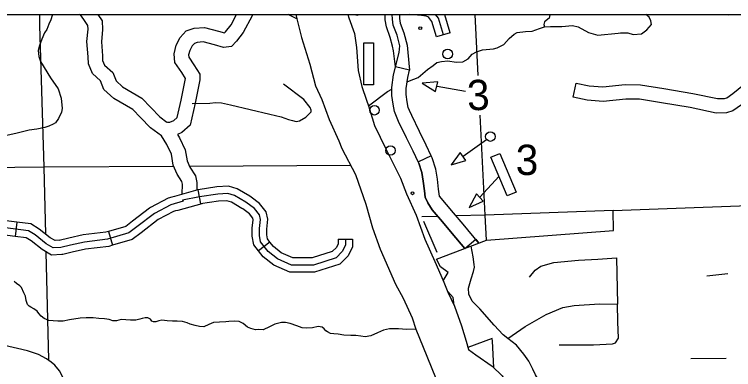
# Model space of a CAD drawing. Extents: x 22866 to 28196, y 1324810 to 1328105.
# Drawn here: x 25465.4 to 25645.9, y 1326492.6 to 1326581.6 of the extents above; entities that cross this region are included whole.
import ezdxf

# ---------------------------------------------------------------- set-up
doc = ezdxf.new("R2010")
doc.units = 0
for name, color, linetype in [('Level 10', 7, 'Continuous'), ('Level 31', 7, 'Continuous'), ('Level 32', 7, 'Continuous'), ('Level 33', 7, 'Continuous'), ('Level 34', 7, 'Continuous'), ('Level 35', 7, 'Continuous'), ('Level 43', 7, 'Continuous'), ('Level 45', 7, 'Continuous'), ('Level 46', 7, 'Continuous'), ('Level 5', 7, 'Continuous'), ('Level 56', 7, 'Continuous'), ('Level 6', 7, 'Continuous'), ('Level 9', 7, 'Continuous'), ('R_No Plot', 7, 'Continuous')]:
    doc.layers.add(name, color=color, linetype=linetype)

msp = doc.modelspace()

# ---------------------------------------------------------------- linework, layer by layer
at = {"layer": 'Level 10'}
msp.add_lwpolyline([(25483.97, 1326486.04), (25481.75, 1326486.89), (25480.32, 1326487.75), (25479.48, 1326488.37), (25478.6, 1326489.1), (25478.14, 1326489.62), (25477.72, 1326490.32), (25476.7, 1326492.23), (25475.5, 1326493.72), (25474.58, 1326494.45), (25473.43, 1326495.3), (25471.42, 1326496.33), (25468.7, 1326497.28), (25466.13, 1326497.87), (25462.9, 1326498.6), (25457.93, 1326499.47), (25456.22, 1326499.8), (25452.62, 1326500.3), (25449.84, 1326500.5), (25447.36, 1326500.74), (25445.63, 1326500.86), (25443.19, 1326500.9), (25441.23, 1326500.79)], dxfattribs=at)
at = {"layer": 'Level 31'}
for p, q in [((25564.54, 1326567.62), (25561.05, 1326568.49)), ((25569.99, 1326546.15), (25566.76, 1326544.65)), ((25578.38, 1326522.93), (25581.15, 1326525.23)), ((25581.15, 1326525.23), (25581.93, 1326524.29))]:
    msp.add_line(p, q, dxfattribs=at)
for points in [[(25558.42, 1326580.72), (25558.4, 1326581.62)], [(25561.05, 1326568.49), (25560.5, 1326572.48), (25560.3, 1326573.63), (25559.71, 1326575.86), (25558.72, 1326578.47), (25558.43, 1326580.29), (25558.42, 1326580.72)], [(25562, 1326581.62), (25562.02, 1326580.8)], [(25562.02, 1326580.8), (25562.03, 1326580.61), (25562.22, 1326579.4), (25563.14, 1326576.96), (25563.95, 1326573.92), (25564.14, 1326572.03), (25564.54, 1326567.62)], [(25561.26, 1326556.06), (25560.75, 1326557.24), (25560.4, 1326559.14), (25560.13, 1326561.27), (25560.09, 1326563.26), (25560.54, 1326566.46), (25561.05, 1326568.49)], [(25564.56, 1326557.5), (25564.21, 1326558.3), (25563.96, 1326559.69), (25563.72, 1326561.53), (25563.7, 1326563.04), (25564.08, 1326565.77), (25564.54, 1326567.62)], [(25569.99, 1326546.15), (25568.73, 1326548.86), (25567.04, 1326552.26), (25565.08, 1326556.3), (25564.56, 1326557.5)], [(25566.73, 1326544.63), (25565.49, 1326547.3), (25563.8, 1326550.67), (25561.81, 1326554.8), (25561.26, 1326556.06)], [(25566.73, 1326544.63), (25566.86, 1326544.34), (25567.65, 1326542), (25567.96, 1326539.8), (25568.27, 1326537.35), (25568.48, 1326535.84), (25569.1, 1326534.36), (25570.24, 1326532.64)], [(25572.08, 1326536.04), (25571.84, 1326537.82), (25571.53, 1326540.28), (25571.17, 1326542.84), (25570.21, 1326545.68), (25569.99, 1326546.15)], [(25581.93, 1326524.29), (25578, 1326529), (25575.56, 1326531.9), (25572.08, 1326536.04)], [(25570.24, 1326532.64), (25570.26, 1326532.61), (25572.81, 1326529.58), (25575.25, 1326526.69), (25578.38, 1326522.93)]]:
    msp.add_lwpolyline(points, dxfattribs=at)
at = {"layer": 'Level 32'}
msp.add_line((25574.76, 1326577.04), (25571.32, 1326575.99), dxfattribs=at)
for points in [[(25571.32, 1326575.99), (25570.15, 1326579.82), (25569.35, 1326580.87), (25569.14, 1326581.04), (25568.75, 1326581.19), (25567.51, 1326581.36), (25564.5, 1326581.62)], [(25573.04, 1326576.52), (25571.78, 1326580.66), (25571.04, 1326581.62)], [(25574.76, 1326577.04), (25573.4, 1326581.49), (25573.3, 1326581.62)]]:
    msp.add_lwpolyline(points, dxfattribs=at)
at = {"layer": 'Level 33'}
for points in [[(25582.2, 1326507.79), (25580.28, 1326509.69), (25579.38, 1326511.51), (25579.31, 1326512.99), (25579.97, 1326515.36), (25580.55, 1326517.15), (25580.86, 1326518.28), (25580.79, 1326518.9), (25580.49, 1326520.84), (25580.01, 1326523.55)], [(25594.68, 1326515.77), (25596.05, 1326517.48), (25597.48, 1326518.51), (25600.76, 1326519.39), (25606.91, 1326520.01), (25611.76, 1326520.28), (25616.48, 1326520.63), (25616.75, 1326509)], [(25589.21, 1326500.38), (25593.59, 1326503.39), (25598.85, 1326506.4), (25603.02, 1326508.11), (25605.82, 1326508.66), (25612.17, 1326509.07), (25616.75, 1326509)], [(25602.13, 1326498.74), (25610.67, 1326498.81), (25615.45, 1326499.01), (25616.21, 1326499.29), (25616.96, 1326500.45), (25616.82, 1326504.55), (25616.75, 1326509)], [(25614.2, 1326465.08), (25609.33, 1326471.93), (25605.93, 1326476.85), (25604.87, 1326478.64), (25603.7, 1326481.15), (25602.67, 1326482.94), (25601.29, 1326485.07), (25599.76, 1326486.94), (25598.01, 1326488.83), (25596.67, 1326490.41), (25596.18, 1326491.23), (25595.46, 1326492.71), (25594.47, 1326494.71), (25593.2, 1326496.46), (25591.37, 1326498.68), (25589.21, 1326500.38), (25588.04, 1326501.26), (25585.77, 1326503.7), (25582.2, 1326507.79)]]:
    msp.add_lwpolyline(points, dxfattribs=at)
at = {"layer": 'Level 34'}
for points in [[(25535.2, 1326555.02), (25536.07, 1326554.81), (25536.91, 1326554.93), (25538.55, 1326555.84), (25539.85, 1326557.22), (25539.85, 1326557.64), (25539.62, 1326558.25), (25537.98, 1326560.27), (25532.94, 1326564.13)], [(25509.97, 1326559.25), (25514.44, 1326559.4), (25515.86, 1326559.51), (25517.38, 1326559.43), (25519.63, 1326558.98), (25529.48, 1326556.61), (25532.29, 1326555.92), (25534.16, 1326555.31), (25535.2, 1326555.02)], [(25639.13, 1326516.05), (25644.42, 1326516.63)], [(25643.96, 1326495.38), (25635.13, 1326495.3)]]:
    msp.add_lwpolyline(points, dxfattribs=at)
at = {"layer": 'Level 35'}
for points in [[(25474.78, 1326581.62), (25474.87, 1326581.36), (25474.55, 1326580.22), (25474.02, 1326579.18), (25473.52, 1326577.86), (25472.95, 1326577.04), (25472.31, 1326575.43), (25471.7, 1326573.83)], [(25536.24, 1326580.53), (25534.1, 1326581.62)], [(25563.94, 1326564.75), (25564.54, 1326564.99), (25566.67, 1326565.77), (25569.03, 1326567.77), (25570.45, 1326568.77), (25571.38, 1326569.56), (25572.59, 1326569.84), (25574.16, 1326569.99), (25576.23, 1326569.63), (25577.94, 1326569.7), (25579.29, 1326570.48), (25580.22, 1326571.63), (25581.36, 1326572.2), (25582.86, 1326572.7), (25585.57, 1326572.98), (25586.57, 1326573.2), (25588.21, 1326574.05), (25589.56, 1326575.55), (25590.77, 1326576.69), (25591.56, 1326577.05), (25593.63, 1326577.34), (25595.34, 1326577.41), (25597.12, 1326578.12), (25598.4, 1326578.48), (25599.9, 1326578.55), (25602.75, 1326578.62), (25605.46, 1326578.84), (25606.89, 1326578.48), (25609.45, 1326577.05), (25611.81, 1326576.41), (25616.86, 1326576.91), (25617.5, 1326576.98), (25619.28, 1326576.98), (25620.63, 1326576.55), (25622.77, 1326576.77), (25624.06, 1326577.76), (25625.27, 1326579.12), (25625.13, 1326579.98), (25624.7, 1326580.91), (25623.85, 1326581.62)], [(25599.67, 1326581.62), (25599.73, 1326581.51), (25599.59, 1326580.65), (25598.45, 1326579.79), (25598.23, 1326579.08), (25598.4, 1326578.48)], [(25641.86, 1326581.62), (25641.88, 1326581.62), (25644.52, 1326581.55), (25645.42, 1326581.62)], [(25471.7, 1326573.83), (25471.38, 1326572.53), (25471.49, 1326571.03), (25471.95, 1326569.78), (25474.48, 1326565.68), (25476.33, 1326562.97), (25477.08, 1326560.65), (25477.33, 1326558.04), (25477.19, 1326557.08), (25476.48, 1326555.51), (25475.73, 1326554.47), (25475.12, 1326554.07), (25474.02, 1326553.61), (25473.05, 1326553.29), (25470.99, 1326552.89), (25469.06, 1326552.64), (25465.78, 1326551.79), (25462.29, 1326551.04)], [(25554.23, 1326558.72), (25558.97, 1326562.28), (25560.1, 1326562.9)], [(25566.13, 1326502.69), (25563.81, 1326502.65), (25561.78, 1326502.76), (25560.25, 1326502.76), (25559.54, 1326502.8), (25558.04, 1326502.48), (25556.47, 1326501.76), (25554.83, 1326501.05), (25553.4, 1326500.76), (25552.3, 1326500.94), (25551.05, 1326501.08), (25549.84, 1326501.16), (25548.02, 1326501.19), (25546.59, 1326501.44), (25545.52, 1326501.51), (25544.67, 1326501.66), (25543.96, 1326502.01), (25543.53, 1326502.3), (25543.14, 1326502.76), (25542.6, 1326503.19), (25541.64, 1326503.37), (25540.18, 1326503.08), (25538.58, 1326502.94), (25537.58, 1326503.05), (25536.23, 1326503.55), (25534.55, 1326504.12), (25533.41, 1326504.37), (25532.41, 1326504.37), (25530.77, 1326503.97), (25529.38, 1326503.26), (25527.85, 1326502.58), (25526.67, 1326502.62), (25525.89, 1326502.58), (25524.71, 1326502.87), (25523.89, 1326503.19), (25522.75, 1326504.12), (25521.79, 1326504.65), (25520.65, 1326504.69), (25519.22, 1326504.62), (25518.4, 1326504.58), (25516.84, 1326504.44), (25515.35, 1326504.37), (25514.17, 1326503.87), (25512.89, 1326503.33), (25511.85, 1326503.4), (25510.75, 1326503.62), (25509.53, 1326503.98), (25508.71, 1326504.26), (25507.57, 1326504.65), (25506.22, 1326504.69), (25505.04, 1326504.69), (25503.72, 1326504.8), (25502.4, 1326504.97), (25501.62, 1326504.83), (25500.91, 1326504.55), (25500.3, 1326504.51), (25499.84, 1326504.72), (25499.52, 1326505.19), (25498.84, 1326505.51), (25498.2, 1326505.55), (25497.45, 1326505.4), (25496.85, 1326505.19), (25495.85, 1326504.94), (25494.53, 1326504.94), (25493.36, 1326505.08), (25492.18, 1326505.12), (25491, 1326504.76), (25490.08, 1326504.83), (25489.15, 1326505.12), (25487.97, 1326505.3), (25486.58, 1326505.4), (25485.16, 1326505.58), (25483.41, 1326505.55), (25481.88, 1326505.44), (25479.24, 1326505.01), (25477.63, 1326504.69), (25476.31, 1326504.72), (25475.1, 1326504.76), (25474.03, 1326504.9), (25472.89, 1326505.37), (25472.11, 1326505.94), (25471.54, 1326506.62), (25471.11, 1326507.22), (25470.29, 1326507.83), (25469.54, 1326508.22), (25469.08, 1326508.47), (25468.65, 1326508.9), (25468.33, 1326509.93), (25468.15, 1326511.01), (25467.76, 1326511.79), (25467.16, 1326513.17), (25466.73, 1326513.6), (25465.87, 1326514.17), (25465.34, 1326514.63)]]:
    msp.add_lwpolyline(points, dxfattribs=at)
at = {"layer": 'Level 43'}
for points in [[(25561.95, 1326572.1), (25562.12, 1326573.77), (25561.42, 1326576.41), (25560.47, 1326578.93), (25560.23, 1326580.45), (25560.2, 1326581.62)], [(25578.38, 1326522.93), (25575.25, 1326526.69), (25572.81, 1326529.58), (25570.26, 1326532.61), (25569.1, 1326534.36), (25568.48, 1326535.84), (25568.27, 1326537.35), (25567.96, 1326539.8), (25567.65, 1326542), (25566.86, 1326544.34), (25565.49, 1326547.3), (25563.8, 1326550.67), (25561.81, 1326554.8), (25560.75, 1326557.24), (25560.4, 1326559.14), (25560.13, 1326561.27), (25560.09, 1326563.26), (25560.54, 1326566.46), (25561.95, 1326572.1)]]:
    msp.add_lwpolyline(points, dxfattribs=at)
at = {"layer": 'Level 45'}
for p, q in [((25511.39, 1326537.64), (25512.07, 1326534.1)), ((25465.98, 1326529.55), (25465.54, 1326525.97)), ((25489.01, 1326527.2), (25490.02, 1326523.75)), ((25546.63, 1326525.24), (25550.23, 1326525.24)), ((25529.52, 1326524.53), (25526.67, 1326522.32))]:
    msp.add_line(p, q, dxfattribs=at)
for points in [[(25511.39, 1326537.64), (25505.56, 1326535.97), (25504.93, 1326535.83), (25504, 1326535.57), (25499.54, 1326533.22), (25499.29, 1326533.02)], [(25524.8, 1326535.77), (25524.45, 1326536.02), (25521.31, 1326537.89), (25519.15, 1326538.52), (25516.22, 1326538.36), (25511.5, 1326537.66), (25511.39, 1326537.64)], [(25548.43, 1326525.24), (25548.43, 1326523.73), (25547.67, 1326522.15), (25546.1, 1326520.58), (25540.4, 1326518.79), (25534.92, 1326518.79), (25531.42, 1326520.3), (25529.09, 1326522.15), (25527.17, 1326524.62), (25526.89, 1326526.2), (25526.89, 1326527.92), (25527.17, 1326530.19), (25526.89, 1326531.35), (25525.66, 1326532.93), (25523.46, 1326534.51), (25520.58, 1326536.23), (25518.94, 1326536.71), (25516.4, 1326536.57), (25511.8, 1326535.88), (25507.55, 1326535.06), (25507.74, 1326534.76), (25504.67, 1326533.89), (25500.51, 1326531.69), (25496.12, 1326528.33), (25494.14, 1326526.82), (25488.72, 1326525.24), (25482.96, 1326524.56), (25479.46, 1326523.8), (25477.06, 1326523.18), (25475.14, 1326523.11), (25473.35, 1326524.14), (25470.61, 1326526.34), (25468.9, 1326527.37), (25461.15, 1326528.33)], [(25529.52, 1326524.53), (25528.86, 1326525.38), (25528.69, 1326526.36), (25528.69, 1326527.81), (25528.99, 1326530.29), (25528.55, 1326532.15), (25526.92, 1326534.24), (25524.8, 1326535.77)], [(25512.38, 1326534.17), (25506.42, 1326532.47), (25505.79, 1326532.34), (25505.34, 1326532.21), (25501.49, 1326530.17), (25501.48, 1326530.17)], [(25522.69, 1326532.85), (25522.47, 1326533), (25519.86, 1326534.56), (25518.73, 1326534.89), (25516.58, 1326534.78), (25512.11, 1326534.11), (25512.07, 1326534.1)], [(25499.29, 1326533.02), (25495.03, 1326529.76), (25493.31, 1326528.46), (25489.01, 1326527.2)], [(25526.67, 1326522.32), (25525.47, 1326523.87), (25525.09, 1326526.05), (25525.09, 1326528.03), (25525.34, 1326530.08), (25525.23, 1326530.55), (25524.4, 1326531.62), (25522.69, 1326532.85)], [(25465.98, 1326529.55), (25461.21, 1326530.14), (25456.83, 1326529.9), (25454.12, 1326528.27), (25453.32, 1326525.41)], [(25501.48, 1326530.17), (25497.22, 1326526.9), (25494.96, 1326525.19), (25490.02, 1326523.75)], [(25476.8, 1326524.98), (25475.59, 1326524.93), (25474.37, 1326525.63), (25471.64, 1326527.82), (25469.5, 1326529.11), (25465.98, 1326529.55)], [(25465.54, 1326525.97), (25461.08, 1326526.52), (25457.92, 1326526.35), (25457.2, 1326525.92), (25456.79, 1326524.45)], [(25489.01, 1326527.2), (25488.36, 1326527.01), (25482.66, 1326526.33), (25479.04, 1326525.55), (25476.63, 1326524.93)], [(25477.52, 1326521.44), (25477.32, 1326521.39), (25474.69, 1326521.3), (25472.34, 1326522.65), (25469.58, 1326524.86), (25468.3, 1326525.63), (25465.54, 1326525.97)], [(25546.63, 1326525.24), (25546.63, 1326524.14), (25546.18, 1326523.21), (25545.13, 1326522.16), (25540.13, 1326520.59), (25539.19, 1326520.59)], [(25550.23, 1326525.24), (25550.23, 1326523.32), (25549.16, 1326521.1), (25547.06, 1326518.99), (25540.68, 1326516.99), (25539.19, 1326516.99)], [(25490.02, 1326523.75), (25489.08, 1326523.47), (25483.25, 1326522.78), (25479.87, 1326522.05), (25477.52, 1326521.44)], [(25539.19, 1326520.59), (25535.29, 1326520.59), (25532.35, 1326521.86), (25530.38, 1326523.43), (25529.52, 1326524.53)], [(25539.19, 1326516.99), (25534.54, 1326516.99), (25530.49, 1326518.74), (25527.8, 1326520.88), (25526.67, 1326522.32)]]:
    msp.add_lwpolyline(points, dxfattribs=at)
at = {"layer": 'Level 46'}
for points in [[(25502.28, 1326551.2), (25499.5, 1326553.18), (25497.06, 1326555.77), (25495.11, 1326557.78), (25490.37, 1326560.57), (25487.85, 1326562.83), (25487.03, 1326564.96), (25484.99, 1326566.79), (25483.96, 1326569.24), (25483.88, 1326570.98), (25483.59, 1326574.81), (25483.87, 1326577.92), (25483.83, 1326578.82), (25482.83, 1326580.34), (25481.95, 1326581.48), (25481.68, 1326581.62)], [(25486.3, 1326581.62), (25487.38, 1326579.97), (25487.48, 1326577.84), (25487.21, 1326574.78), (25487.47, 1326571.2), (25487.53, 1326570.05), (25488, 1326568.93), (25490.08, 1326567.06), (25490.9, 1326564.93), (25492.5, 1326563.49), (25497.36, 1326560.64), (25499.66, 1326558.26), (25501.88, 1326555.91), (25503.66, 1326554.64)], [(25503.4, 1326554.79), (25503.83, 1326554.58), (25504.39, 1326554.58), (25505.38, 1326555.06), (25506.25, 1326555.81), (25507.22, 1326560.08), (25508.28, 1326565.58), (25508.28, 1326565.59), (25507.4, 1326567.04), (25505.66, 1326569.58), (25505.44, 1326571.72), (25505.98, 1326573.88), (25507.02, 1326575.87), (25508.51, 1326577.47), (25510.53, 1326578.17), (25513.13, 1326578.35), (25516.59, 1326577.44), (25518.11, 1326576.99), (25518.37, 1326577.29), (25519.75, 1326579.04), (25521.16, 1326581.62)], [(25525.1, 1326581.62), (25525.06, 1326581.25), (25522.76, 1326577.05), (25521.12, 1326574.95), (25519.88, 1326573.6), (25517.82, 1326573.32), (25515.63, 1326573.97), (25512.78, 1326574.72), (25511.26, 1326574.61), (25510.54, 1326574.36), (25509.98, 1326573.76), (25509.37, 1326572.59), (25509.09, 1326571.46), (25509.15, 1326570.86), (25510.42, 1326569), (25511.88, 1326566.6), (25511.88, 1326565.24), (25510.74, 1326559.35), (25509.51, 1326553.87), (25507.37, 1326552.02), (25506.31, 1326551.51)], [(25673.9, 1326581.62), (25671.53, 1326578.71), (25666.92, 1326572.58), (25662.5, 1326565.57), (25659.81, 1326562.61), (25657.1, 1326562.03), (25654.6, 1326561.8), (25652.23, 1326561.73), (25650.85, 1326561.42), (25647.85, 1326558.95), (25645.71, 1326557.41), (25644.1, 1326556.98), (25641.49, 1326556.89), (25634.96, 1326558.24), (25627.78, 1326559.48), (25622.22, 1326560.34), (25618.8, 1326560.4), (25613.13, 1326559.81), (25609.12, 1326560.13), (25605.57, 1326560.88)], [(25605.57, 1326560.88), (25606.32, 1326564.41), (25609.64, 1326563.7), (25613.08, 1326563.43), (25618.65, 1326564.01), (25622.53, 1326563.93), (25628.36, 1326563.03), (25635.63, 1326561.78), (25641.8, 1326560.51), (25643.57, 1326560.56), (25644.14, 1326560.72), (25645.65, 1326561.81), (25649.23, 1326564.75), (25651.78, 1326565.32), (25654.38, 1326565.39), (25656.55, 1326565.6), (25657.93, 1326565.89), (25659.62, 1326567.76), (25663.96, 1326574.63), (25668.69, 1326580.92), (25669.26, 1326581.62)], [(25507.51, 1326536.53), (25507.58, 1326539.1), (25507.44, 1326539.73), (25506.22, 1326541.59), (25505.25, 1326543.85), (25504.78, 1326546.56), (25503.62, 1326549), (25502.28, 1326551.2)], [(25506.31, 1326551.51), (25506.79, 1326550.71), (25508.24, 1326547.66), (25508.73, 1326544.88), (25509.4, 1326543.3), (25510.79, 1326541.17), (25511.2, 1326539.47), (25511.14, 1326537.57)]]:
    msp.add_lwpolyline(points, dxfattribs=at)
at = {"layer": 'Level 5'}
for points in [[(25472.87, 1326543.36), (25471.78, 1326578.84), (25471.76, 1326581.62)], [(25581.78, 1326566.29), (25581.02, 1326581.62)], [(25583.52, 1326531.3), (25582.28, 1326556.35)], [(25472.87, 1326543.36), (25347.76, 1326541.88)], [(25505.4, 1326543.51), (25472.87, 1326543.36)], [(25473.28, 1326526.51), (25472.87, 1326543.36)], [(25549.78, 1326543.73), (25509.25, 1326543.53)], [(25615.63, 1326532.48), (25583.52, 1326531.3)], [(25571.64, 1326530.97), (25567.62, 1326530.86)], [(25583.52, 1326531.3), (25576.24, 1326531.1)], [(25583.88, 1326525.03), (25583.52, 1326531.3)], [(25474.04, 1326494.98), (25473.39, 1326522.05)]]:
    msp.add_lwpolyline(points, dxfattribs=at)
at = {"layer": 'Level 56'}
for p, q in [((25571.46, 1326563.63), (25578.55, 1326562.4)), ((25577.96, 1326546.09), (25583.83, 1326550.26)), ((25582.16, 1326535.8), (25587.06, 1326541.08))]:
    msp.add_line(p, q, dxfattribs=at)
for points in [[(25553.08, 1326574.46), (25555.48, 1326574.46), (25555.48, 1326563.96), (25553.08, 1326563.96)], [(25571.03, 1326562.31), (25571.61, 1326564.69), (25567.75, 1326564.37)], [(25578.67, 1326545.03), (25577.25, 1326547.03), (25574.96, 1326543.91)], [(25584.98, 1326545.82), (25587.19, 1326546.76), (25591.28, 1326537.08), (25589.07, 1326536.15)], [(25583.03, 1326534.84), (25581.33, 1326536.6), (25579.54, 1326533.17)]]:
    msp.add_lwpolyline(points, close=True, dxfattribs=at)
msp.add_lwpolyline([(25568.06, 1326529.79), (25571.36, 1326521.98)], dxfattribs=at)
for centre, radius in [((25567.24, 1326578.16), 0.36), ((25574.11, 1326571.69), 1.2), ((25555.75, 1326557.6), 1.2), ((25584.83, 1326550.99), 1.2), ((25559.76, 1326547.5), 1.2), ((25565.28, 1326536.78), 0.36)]:
    msp.add_circle(centre, radius, dxfattribs=at)
msp.add_arc((25551.38, 1326582.67), 1.2, 241.1159, 298.8841, dxfattribs=at)
at = {"layer": 'Level 6'}
for points in [[(25572.97, 1326514.86), (25574.2, 1326516.9), (25572.33, 1326518.36), (25571.34, 1326520.23), (25583.88, 1326525.03), (25615.74, 1326527.46), (25615.63, 1326532.48), (25710.68, 1326535.98), (25710.69, 1326528.85), (25724.48, 1326529.27)], [(25575.71, 1326508.75), (25575.48, 1326510.63), (25574.12, 1326512.14)], [(25585.71, 1326493.08), (25585.33, 1326499.66), (25585.29, 1326500.4), (25579.15, 1326498.14)]]:
    msp.add_lwpolyline(points, dxfattribs=at)
at = {"layer": 'Level 9'}
for points in [[(25536.04, 1326581.62), (25536.24, 1326580.53), (25537.46, 1326575.84), (25539.5, 1326569.12), (25540.92, 1326563.68), (25542.55, 1326560.29), (25544.38, 1326555.26), (25546.76, 1326549.89), (25547.57, 1326547.99)], [(25549.04, 1326581.62), (25549.34, 1326580.74), (25550.7, 1326576.8), (25551.24, 1326573.33), (25551.65, 1326567.56), (25552.6, 1326563.55), (25553.75, 1326560.08), (25554.23, 1326558.72), (25555.79, 1326553.76)], [(25555.79, 1326553.76), (25558.57, 1326547.9), (25562.3, 1326540.56), (25563.8, 1326536.62), (25566.17, 1326531.32), (25568.41, 1326525.28), (25570.86, 1326519.7), (25572.96, 1326514.88)], [(25547.57, 1326547.99), (25550.97, 1326541.45), (25553.61, 1326534.04), (25555.24, 1326528.13), (25557.21, 1326522.76), (25561.01, 1326514)], [(25561.01, 1326514), (25562.91, 1326510.51), (25565.22, 1326505.55), (25566.13, 1326502.69), (25568.89, 1326495.97), (25571.26, 1326490.19), (25572.48, 1326487.13), (25573.84, 1326484.42), (25575.06, 1326482.31)], [(25572.96, 1326514.88), (25574.18, 1326512), (25575.81, 1326508.47), (25577.58, 1326503.58), (25578.73, 1326499.7), (25579.3, 1326497.6)], [(25579.3, 1326497.6), (25581.17, 1326496.26), (25585.24, 1326493.41), (25587.75, 1326490.97), (25590.47, 1326486.41), (25593.52, 1326481.39)]]:
    msp.add_lwpolyline(points, dxfattribs=at)
at = {"layer": 'R_No Plot'}
msp.add_lwpolyline([(24815.02, 1326581.62), (26086.71, 1326581.62), (26086.71, 1325755.52), (24815.02, 1325755.52)], close=True, dxfattribs=at)
msp.add_lwpolyline([(24815.02, 1326581.62), (26086.71, 1326581.62), (26086.71, 1325755.52), (24815.02, 1325755.52)], close=True, dxfattribs=at)

# ---------------------------------------------------------------- texts
at = {"layer": 'Level 56'}
msp.add_text('3', height=7.6, rotation=2.0474, dxfattribs=at).set_placement((25579.1, 1326557.53))
msp.add_text('3', height=7.6, dxfattribs=at).set_placement((25591.19, 1326541.36))

doc.saveas('drawing.dxf')
